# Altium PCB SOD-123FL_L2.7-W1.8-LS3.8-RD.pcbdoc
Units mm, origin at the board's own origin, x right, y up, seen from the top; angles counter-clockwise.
Board outline 17.17 x 14.7 mm, 2 copper layers (Top Layer, Bottom Layer), stack 0 mm thick; 1 components, 0 nets, 2 pads, 0 vias.
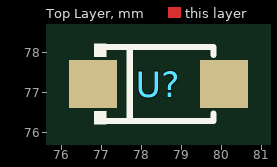
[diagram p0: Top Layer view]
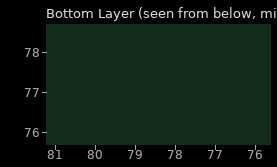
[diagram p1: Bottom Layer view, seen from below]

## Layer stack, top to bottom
Top Layer: signal copper (thickness not stored)
Bottom Layer: signal copper (thickness not stored)

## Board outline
87.02,69.85 69.85,69.85 69.85,84.555 87.02,84.555

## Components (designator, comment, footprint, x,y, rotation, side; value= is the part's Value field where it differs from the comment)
U? "" SOD-123FL_L2.7-W1.8-LS3.8-RD 78.435,77.202 r0 top

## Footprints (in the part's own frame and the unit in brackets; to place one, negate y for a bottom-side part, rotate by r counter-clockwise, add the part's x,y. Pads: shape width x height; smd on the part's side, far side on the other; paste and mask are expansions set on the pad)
SOD-123FL_L2.7-W1.8-LS3.8-RD [mm]
  rect 1.2x1.2 smd: 1(-1.635,0) 2(1.635,0)
  silkscreen extent -1.6,-1 1.38,1

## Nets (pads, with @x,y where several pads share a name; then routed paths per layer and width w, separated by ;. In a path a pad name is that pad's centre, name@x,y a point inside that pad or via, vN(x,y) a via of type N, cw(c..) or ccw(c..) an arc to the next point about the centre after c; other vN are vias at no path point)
pads on no net: U?.1 U?.2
